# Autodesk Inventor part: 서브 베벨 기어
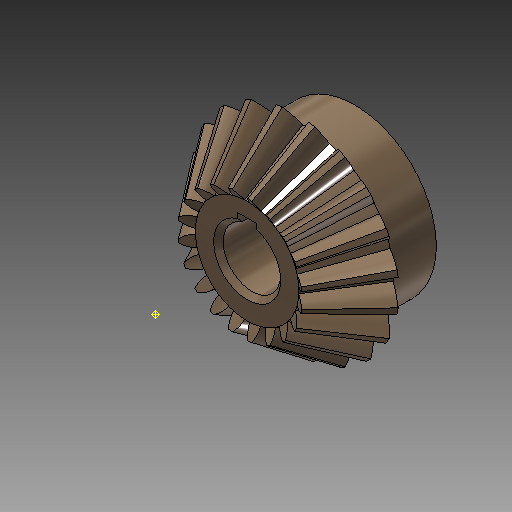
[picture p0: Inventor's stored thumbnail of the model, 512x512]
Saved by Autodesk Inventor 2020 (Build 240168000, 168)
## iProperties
CustomPartVersion: 1
Created: 2016-04
Part Number: 서브 베벨 기어
Material: 강철, 탄소
Document SubType Name: Modeling
Designer: mdu
Categories: <?xml version="1.0" encoding="UTF-16"?> <MemberInstance><Categories><FamilyTemplate><FamilyTemplateParameter ValueType="xs:double" Id="1" ObjectReferenceKey="da
Mass: 135.037 g
Surface Area: 63.6518 cm^2
Volume: 17.1585 cm^3
Density: 7.87 g/cm^3
Appearance: 얼룩무늬
Author: mdu
Revision Number: 1
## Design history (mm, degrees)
node "맨 위 점"
node "메쉬 평면2"
sketch "톱니 본체 스케치"
  geometry: L1 (0, 0)-(18.003, -31.331); L2 (18.003, -31.331)-(21.664, -28.891); L3 (21.664, -28.891)-(0, 0); L4 (20, -30)-(0, 0); L5 (10.813, -18.818)-(13.012, -17.352); L6 (18.003, -31.331)-(10.813, -18.818); L7 (21.664, -28.891)-(13.012, -17.352); L8 (0, -39.387)-(0, 6.564) reference; L9 (0, -30)-(21.664, -30)
  constraints: 16 end point, 4 point on line, 3 perpendicular, 2 collinear, 1 horizontal alignment, 1 vertical alignment
  dimensions: "d0" = 40 diameter of L4.start L8 (= da_de); "d1" = 36.00616 diameter of L1.end L8 (= da_dfe); "d2" = 43.3282 diameter of L2.end L8 (= da_dae); "d3" = 14.4 distance between parallel lines of L2 L5 (= da_b); "d4" = 28.8906 vertical distance of L2.end L1.start (= da_ve)
revolve "톱니 본체" sketch "톱니 본체 스케치" stored, may be unused: angle "d5" = 90 deg
node "시작점"
node "톱니 평면"
sketch "시작 스케치"
  geometry: L1 (0, -23.505)-(0, 10.645) reference; L2 (-0.834, -2.928)-(0.834, -2.928); A1 r 8.898 centre (-9.698, -3.713) between (-0.834, -2.928) and (-3.903, 3.04); A2 r 8.898 centre (9.698, -3.713) between (3.903, 3.04) and (0.834, -2.928); A3 r 27.357 centre (0, -24.037) between (3.903, 3.04) and (-3.903, 3.04); 1 further point
  constraints: 6 point on circle, 3 centre point, 3 symmetric about line, 2 end point, 1 coincident, 1 perpendicular, 1 other
  dimensions: "d7" = 8.89846 radius of A1 (= fd_rr); "d8" = 9.69794 horizontal distance of point (0, -24.037) A1.centre (= fd_x); "d9" = 20.32439 vertical distance of point (0, -24.037) A1.centre (= fd_y); "d57" = 27.35701 radius of A3 (= 0.5 x fd_dva + 0.3 x da_he); "d58" = 21.10901 distance from line of A3.centre L2 (= 0.5 x fd_dva - 1.12 x da_he)
node "끝점"
  node "끝 평면"
sketch "3D 스케치 오른쪽"
  node "Helical Curve Right" dims "d65" = 229.90621 (computed from da_dm, da_delta, da_beta), "d66" = 31.5, "d67" = 40 (= da_de), "d68" = -5.88003 (= -da_delta), "d69" = 12.16458 (computed from fd_loft, da_delta)
node "끝 평면 오른쪽"
sketch "끝 스케치 오른쪽"
  geometry: L1 (0, -22.649)-(0, 12.15) reference; L2 (-0.497, -1.72)-(0.497, -1.72); A1 r 5.299 centre (-5.775, -2.187) between (-0.497, -1.72) and (-2.324, 1.834); A2 r 5.299 centre (5.775, -2.187) between (2.324, 1.834) and (0.497, -1.72); A3 r 16.291 centre (0, -14.29) between (2.324, 1.834) and (-2.324, 1.834); 1 further point
  constraints: 6 point on circle, 3 centre point, 3 symmetric about line, 2 end point, 1 coincident, 1 perpendicular, 1 other
  dimensions: "d70" = 5.77526 horizontal distance of A3.centre A1.centre (computed from fd_x, fd_ratio); "d71" = 12.10346 vertical distance of point (0, -14.29) A1.centre (computed from fd_y, fd_ratio); "d72" = 5.29916 radius of A1 (computed from fd_rr, fd_ratio); "d73" = 12.57071 distance from line of point (0, -14.29) L2 (computed from d58, fd_ratio); "d74" = 16.29149 radius of A3 (computed from d57, fd_ratio)
feature "로프트 오른쪽" sketch "끝 스케치 오른쪽" dims "d75" = 0, "d77" = 0, "d79" = 0, "d80" = 90 deg, "d85" = 20, "d92" = 90 deg, "d93" = 90 deg, "da_teethtype" = 0 [user parameter]
sketch "3D 스케치 왼쪽"
  node "Helical Curve Left" dims "d26" = 229.90621 (computed from da_dm, da_delta, da_beta), "d27" = 12.16458 (computed from fd_loft, da_delta), "d28" = 40 (= da_de), "d29" = -5.88003 (= -da_delta)
node "끝 평면 왼쪽"
sketch "끝 스케치 왼쪽" dims "d56" = 10.82768 (derived)
  geometry: L1 (0, -35.087)-(0, 18.089) reference; L2 (-0.497, -1.716)-(0.497, -1.716); A1 r 5.299 centre (-5.775, -2.183) between (-0.497, -1.716) and (-2.324, 1.838); A2 r 5.299 centre (5.775, -2.183) between (2.324, 1.838) and (0.497, -1.716); A3 r 16.291 centre (0, -14.287) between (2.324, 1.838) and (-2.324, 1.838); 2 further points; 1 other entity
  constraints: 6 point on circle, 3 centre point, 3 symmetric about line, 2 end point, 1 coincident, 2 other
  dimensions: "d30" = 5.29916 radius of A1 (computed from fd_rr, fd_ratio); "d31" = 5.77526 horizontal distance of point (0, -14.287) A1.centre (computed from fd_x, fd_ratio); "d32" = 12.10346 vertical distance of A1.centre point (0, -14.287) (computed from fd_y, fd_ratio); "d61" = 16.29149 radius of A3 (computed from d57, fd_ratio); "d62" = 12.57071 distance from line of point (0, -14.287) L2 (computed from d58, fd_ratio)
feature "로프트 왼쪽" sketch "끝 스케치 왼쪽" dims "d35" = 0, "d37" = 0, "d39" = 0, "d40" = 90 deg, "d84" = 10, "d90" = 90 deg, "d91" = 90 deg, "da_teethtype" = 0 [user parameter]
sketch "본체 스케치"
  geometry: L1 (0, -35.038)-(0, -19.531) reference; L2 (18.003, -31.331)-(10.813, -18.818) reference; L3 (10.813, -18.818)-(0, -18.818); L4 (18.003, -31.331)-(0, -31.331)
  constraints: 4 end point, 2 perpendicular, 2 point on line
revolve "본체 고정" sketch "본체 스케치" stored, may be unused: angle "d46" = 90 deg
feature "피치 지름" dims angle "d47" = 90 deg
sketch "스케치8"
  geometry: C1 r 17 at (0, 0); 1 further point
  constraints: 1 centre point, 1 coincident
  dimensions: "d94" = 34 diameter of C1
extrude "돌출1" join sketch "스케치8" distance "d95" = 10; taper "d96" = 0 deg
sketch "스케치9"
  geometry: 1 further point
hole "구멍1" sketch "스케치9" at (0, 0) diameter "d97" = 12; stored, may be unused: countersink angle "d101" = 90 deg, drill point angle "d103" = 118 deg; dims "d98" = 6, "d99" = 4, "d100" = 2, "d102" = 8
sketch "스케치10"
  geometry: 1 further point
sketch "스케치11"
  geometry: 1 further point
sketch "스케치12"
  geometry: L1 (-2, 5.657)-(-2, 7.8); L2 (-2, 7.8)-(2, 7.8); L3 (2, 7.8)-(2, 5.657); A1 r 6 centre (0, 0) between (-2, 5.657) and (2, 5.657) reference; 1 further point
  constraints: 6 end point, 2 parallel, 2 point on circle, 1 perpendicular, 1 vertical
  dimensions: "d104" = 4 distance of L1.end L2.end; "d105" = 13.8 dimension on A1 L2
extrude "돌출2" cut sketch "스케치12" extent not by distance; stored distance "d106" = 7; taper "d107" = 0 deg
chamfer "모따기1" distance "d108" = 1; stored, may be unused: second distance "d109" = 2, angle "d110" = 45 deg
body "Solid1"
feature "로프트" dims "d17" = 0, "d18" = 90 deg, "d19" = 0, "d20" = 90 deg, "d89" = 0, "da_teethtype" = 0 [user parameter]
pattern_circular "원형 패턴" dims angle "d22" = 360 deg, "d88" = 0, "da_teethtype" = 0 [user parameter]
pattern_circular "원형 패턴 오른쪽" dims angle "d82" = 360 deg, "da_teethtype" = 0 [user parameter]
pattern_circular "원형 패턴 왼쪽" dims angle "d42" = 360 deg, "da_teethtype" = 0 [user parameter]
sketch "끝 스케치"
  geometry: L1 (0, -15.359)-(0, 6.983) reference; L2 (-0.497, -1.72)-(0.497, -1.72); A1 r 5.299 centre (-5.775, -2.187) between (-0.497, -1.72) and (-2.324, 1.834); A2 r 5.299 centre (5.775, -2.187) between (2.324, 1.834) and (0.497, -1.72); A3 r 16.291 centre (0, -14.29) between (2.324, 1.834) and (-2.324, 1.834); 1 further point
  constraints: 6 point on circle, 3 centre point, 3 symmetric about line, 2 end point, 1 coincident, 1 other
  dimensions: "d12" = 5.29916 radius of A1 (computed from fd_rr, fd_ratio); "d15" = 5.77526 horizontal distance of A1.centre point (0, -14.29) (computed from fd_x, fd_ratio); "d16" = 12.10346 vertical distance of A1.centre point (0, -14.29) (computed from fd_y, fd_ratio); "d59" = 16.29149 radius of A3 (computed from d57, fd_ratio); "d60" = 12.57071 distance from line of A3.centre L2 (computed from d58, fd_ratio)
sketch "Sketch6"
  geometry: L1 (20, -30)-(0, 0) reference; L2 (0, -37.8)-(0, 6.3) reference
body "Srf1"
other parameters: "da_b" = 14.4 [user parameter; used in 2 equation terms], "da_de" = 40 [user parameter; used in 4 equation terms], "da_dae" = 43.3282 [user parameter; used in 2 equation terms], "da_dfe" = 36.00616 [user parameter; used in 1 equation term], "da_le" = 36.05551 [user parameter; used in 1 equation term], "da_omega" = 90 deg [user parameter; used in 1 equation term], "da_beta" = 0 [user parameter; used in 2 equation terms], "da_delta" = 5.88003 [user parameter; used in 8 equation terms], "da_alpha" = 20 deg [user parameter; used in 2 equation terms], "da_he" = 4.4 [user parameter; used in 4 equation terms], "da_ve" = 28.8906 [user parameter; used in 1 equation term], "fd_dv" = 48.07402 (computed from da_de, da_delta) [user parameter; used in 1 equation term], "fd_dva" = 52.07402 (computed from da_dae, da_delta) [user parameter; used in 3 equation terms], "fd_dvb" = 45.1748 (computed from fd_dv, da_alpha) [user parameter; used in 2 equation terms], "da_zv" = 240.37008 [user parameter; used in 1 equation term], "fd_loft" = 14.62 (= da_b + 0.05 x da_he) [user parameter; used in 4 equation terms], "fd_ratio" = 5.95514 (computed from da_le, fd_loft) [user parameter; used in 15 equation terms], "fd_rr" = 8.89846 (computed from fd_dd, fd_dvb) [user parameter; used in 6 equation terms], "fd_angle" = 0.66075 (computed from da_zv) [user parameter; used in 4 equation terms], "fd_x1" = 1.58709 (computed from da_dvw, fd_angle) [user parameter; used in 1 equation term], "fd_y1" = 23.98456 (computed from da_dvw, fd_angle) [user parameter; used in 1 equation term], "fd_x2" = 8.11084 (computed from fd_rr, fd_angle2, fd_angle) [user parameter; used in 1 equation term], "fd_y2" = 3.66016 (computed from fd_rr, fd_angle2, fd_angle) [user parameter; used in 1 equation term], "fd_x" = 9.69794 (= fd_x1 + fd_x2) [user parameter; used in 4 equation terms], "fd_y" = 20.32439 (= fd_y1 - fd_y2) [user parameter; used in 4 equation terms], "fd_angle2" = 3.57832 (computed from fd_dvb, fd_dd, da_alpha) [user parameter; used in 2 equation terms], "fd_dd" = 48.55402 (= fd_dva - 0.8 x da_he) [user parameter; used in 2 equation terms], "da_dvw" = 48.07402 [user parameter; used in 2 equation terms], "d11" = 14.62 (= fd_loft), "da_dm" = 32.01232 [user parameter; used in 2 equation terms], "da_x" = 0 [user parameter], "da_m" = 2 [user parameter], "d48" = 0, "d49" = 0, "d50" = 90 deg (= da_omega), "d51" = 9 deg (computed from da_z), "d52" = 0, "d53" = 0, "d54" = 0
